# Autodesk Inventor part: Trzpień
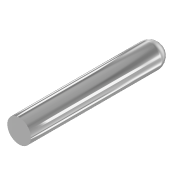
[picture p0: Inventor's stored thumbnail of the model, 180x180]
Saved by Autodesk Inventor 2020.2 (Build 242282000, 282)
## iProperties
Created: 2005-10
Part Number: Trzpień
Document SubType Name: Modeling
Designer: F.Stasiak
Density: 1 g/cm^3
Material: Ogólny
Appearance: Chrom — polerowany
Manager: www.cadconsulting.pl
Company: Fabian Stasiak CAD Consulting
Author: F.Stasiak
Subject: Zbiór ćwiczeń. Autodesk Inventor 2020. Kurs podstawowy
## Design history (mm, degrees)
sketch "Szkic1"
  geometry: L1 (17.877, -4.063)-(17.877, -34.063); L2 (17.877, -34.063)-(20.377, -34.063); L3 (20.377, -34.063)-(20.377, -6.563); A1 r 2.5 centre (17.877, -6.563) between (20.377, -6.563) and (17.877, -4.063)
  constraints: 6 end point, 2 point on circle, 1 centre point, 1 parallel, 1 perpendicular, 1 tangent, 1 vertical
  dimensions: "d0" = 30 distance of L1.start L1.end; "d1" = 2.5 distance of L1.end L2.end; "d2" = 2.5 radius of A1 (= d1)
revolve "Obrót1" sketch "Szkic1" stored, may be unused: angle "d3" = 90 deg
node "Bryła1"
node "Korpusy bryłowe"
node "Korpusy powierzchniowe"
